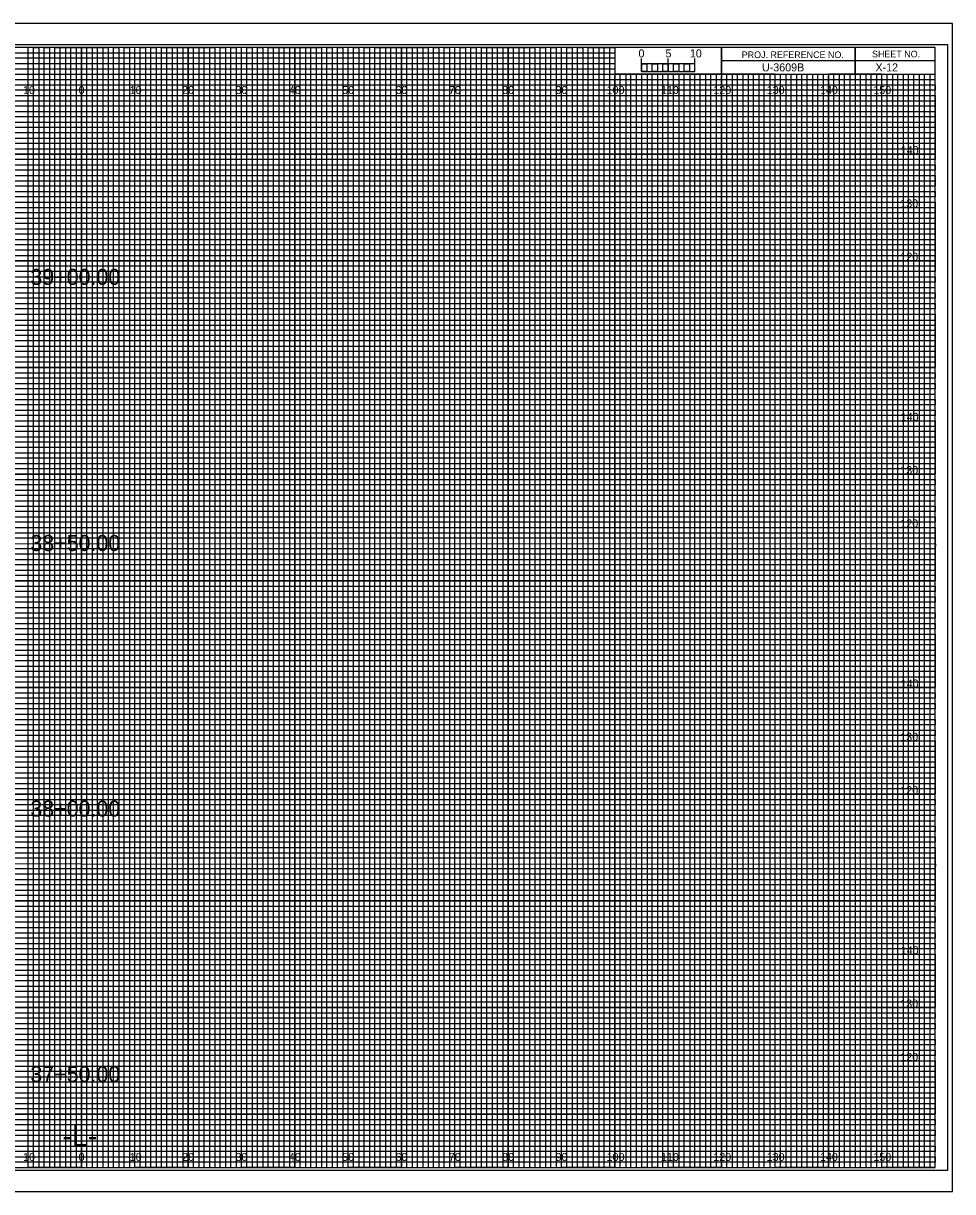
# Model space of a CAD drawing. Extents: x -13 to 329, y -17 to 10994.
# Drawn here: x 149.1 to 323.3, y 2195.5 to 2414.5 of the extents above; entities that cross this region are included whole.
import ezdxf

# ---------------------------------------------------------------- set-up
doc = ezdxf.new("R2010")
doc.units = 0
for name, color, linetype in [('Prop XS Alignment Label', 7, 'Continuous'), ('Prop XS Bar Scale Labels', 7, 'Continuous'), ('Prop XS Elevation Labels', 7, 'Continuous'), ('Prop XS Offset Labels', 7, 'Continuous'), ('Prop XS Project Number', 7, 'Continuous'), ('Prop XS Sheet Number', 7, 'Continuous'), ('Prop XS Station Labels', 7, 'Continuous'), ('Sheet Cross Section CELL', 7, 'Continuous'), ('Sheet Cross Section Grid Major CELL', 7, 'Continuous'), ('Sheet Cross Section Grid Middle CELL', 7, 'Continuous'), ('Sheet Cross Section Grid Minor 1 CELL', 7, 'Continuous'), ('Sheet Cross Section Grid Minor 2 CELL', 7, 'Continuous'), ('Sheet Cross Section Scale CELL', 7, 'Continuous'), ('Sheet Cutting Line CELL', 7, 'Continuous'), ('Sheet DOT Grid CELL', 7, 'Continuous'), ('Sheet Plot Border Inside CELL', 7, 'Continuous'), ('Sheet Plot Border Outside CELL', 7, 'Continuous')]:
    doc.layers.add(name, color=color, linetype=linetype)

msp = doc.modelspace()

# ---------------------------------------------------------------- linework, layer by layer
at = {"layer": 'Sheet Cross Section CELL'}
for p, q in [((305, 2410), (305, 2405)), ((305, 2405), (305, 2410)), ((280, 2407.5), (280, 2405)), ((320, 2407.49), (280, 2407.49)), ((280, 2405), (320, 2405))]:
    msp.add_line(p, q, dxfattribs=at)
for points in [[(320, 2410), (0, 2410), (0, 2200), (320, 2200)], [(280, 2410), (260, 2410), (260, 2405.03), (280, 2405.03)], [(320, 2410), (280, 2410), (280, 2405), (320, 2405)]]:
    msp.add_lwpolyline(points, close=True, dxfattribs=at)
at = {"layer": 'Sheet Cross Section Grid Major CELL'}
for p, q in [((150, 2410), (140, 2410)), ((150, 2200), (150, 2410)), ((170, 2410), (160, 2410)), ((160, 2410), (160, 2200)), ((170, 2200), (170, 2410)), ((190, 2410), (180, 2410)), ((180, 2410), (180, 2200)), ((190, 2200), (190, 2410)), ((210, 2410), (200, 2410)), ((200, 2410), (200, 2200)), ((210, 2200), (210, 2410)), ((230, 2410), (220, 2410)), ((220, 2410), (220, 2200)), ((230, 2200), (230, 2410)), ((250, 2410), (240, 2410)), ((240, 2410), (240, 2200)), ((250, 2200), (250, 2410)), ((260, 2410), (260, 2200)), ((270, 2200), (270, 2405)), ((290, 2405), (280, 2405)), ((280, 2405), (280, 2200)), ((290, 2200), (290, 2405)), ((310, 2405), (300, 2405)), ((300, 2405), (300, 2200)), ((310, 2200), (310, 2405)), ((160, 2200), (150, 2200)), ((180, 2200), (170, 2200)), ((200, 2200), (190, 2200)), ((220, 2200), (210, 2200)), ((240, 2200), (230, 2200)), ((260, 2200), (250, 2200)), ((280, 2200), (270, 2200)), ((300, 2200), (290, 2200)), ((320, 2200), (310, 2200)), ((320, 2200), (320, 2200))]:
    msp.add_line(p, q, dxfattribs=at)
for points in [[(0, 2400), (320, 2400), (320, 2390), (0, 2390)], [(0, 2380), (320, 2380), (320, 2370), (0, 2370)], [(0, 2360), (320, 2360), (320, 2350), (0, 2350)], [(0, 2340), (320, 2340), (320, 2330), (0, 2330)], [(0, 2320), (320, 2320), (320, 2310), (0, 2310)], [(0, 2300), (320, 2300), (320, 2290), (0, 2290)], [(0, 2280), (320, 2280), (320, 2270), (0, 2270)], [(0, 2260), (320, 2260), (320, 2250), (0, 2250)], [(0, 2240), (320, 2240), (320, 2230), (0, 2230)], [(0, 2220), (320, 2220), (320, 2210), (0, 2210)]]:
    msp.add_lwpolyline(points, dxfattribs=at)
at = {"layer": 'Sheet Cross Section Grid Middle CELL'}
for points in [[(145, 2200), (155, 2200), (155, 2410), (165, 2410), (165, 2200), (175, 2200), (175, 2410), (185, 2410), (185, 2200), (195, 2200), (195, 2410), (205, 2410), (205, 2200), (215, 2200), (215, 2410), (225, 2410), (225, 2200), (235, 2200), (235, 2410), (245, 2410), (245, 2200), (255, 2200), (255, 2410), (259.93, 2410), (260, 2410), (260, 2405), (264.99, 2405), (264.99, 2200), (275, 2200), (275, 2405), (285, 2405), (285, 2200), (295, 2200), (295, 2405), (305, 2405), (305, 2200), (315, 2200), (315, 2405)], [(0, 2405), (275, 2405)], [(0, 2385), (320, 2385), (320, 2395), (0, 2395)], [(0, 2365), (320, 2365), (320, 2375), (0, 2375)], [(0, 2345), (320, 2345), (320, 2355), (0, 2355)], [(0, 2325), (320, 2325), (320, 2335), (0, 2335)], [(0, 2305), (320, 2305), (320, 2315), (0, 2315)], [(0, 2285), (320, 2285), (320, 2295), (0, 2295)], [(0, 2265), (320, 2265), (320, 2275), (0, 2275)], [(0, 2245), (320, 2245), (320, 2255), (0, 2255)], [(0, 2225), (320, 2225), (320, 2235), (0, 2235)], [(0, 2205), (320, 2205), (320, 2215), (0, 2215)]]:
    msp.add_lwpolyline(points, dxfattribs=at)
at = {"layer": 'Sheet Cross Section Grid Minor 1 CELL'}
for p, q in [((0, 2409), (260, 2409)), ((260, 2409), (260, 2407.98)), ((260, 2407.98), (0, 2407.98)), ((0, 2407), (260, 2407)), ((260, 2407), (260, 2405.89)), ((260, 2405.89), (0, 2405.89)), ((0, 2404), (320, 2404))]:
    msp.add_line(p, q, dxfattribs=at)
for points in [[(0, 2403), (270, 2403), (320, 2403), (320, 2402), (0, 2402)], [(0, 2401), (320, 2401), (320, 2399), (0, 2399)], [(0, 2398), (320, 2398), (320, 2397), (0, 2396.98)], [(0, 2396), (320, 2396), (320, 2394), (0, 2394)], [(0, 2393), (320, 2393), (320, 2392), (0, 2392)], [(0, 2391), (320, 2391), (320, 2389), (0, 2389)], [(0, 2388), (320, 2388), (320, 2387), (0, 2387)], [(0, 2386), (320, 2386), (320, 2384), (0, 2384)], [(0, 2383), (320, 2383), (320, 2382), (0, 2382)], [(0, 2381), (320, 2381), (320, 2379), (0, 2379)], [(0, 2378), (320, 2378), (320, 2377), (0, 2377)], [(0, 2376), (320, 2376), (320, 2373.95), (320, 2373), (320, 2372), (0, 2372)], [(0, 2374), (320, 2374), (320, 2373), (0, 2373)], [(0, 2371), (320, 2371), (320, 2369), (0, 2369.03)], [(0, 2369.03), (320, 2369), (320, 2368), (0, 2368)], [(0, 2367), (320, 2367), (320, 2366), (0, 2366)], [(0, 2364), (320, 2364), (320, 2363), (0, 2363)], [(0, 2362), (320, 2362), (320, 2361), (0, 2361)], [(-0.07, 2358.89), (320, 2358.89), (320, 2357.88), (-0.07, 2357.88)], [(0, 2357), (320, 2357), (320, 2356), (0, 2356)], [(0, 2354), (320, 2354), (320, 2353), (0, 2353)], [(0, 2352), (320, 2352), (320, 2351), (0, 2351)], [(0, 2349), (320, 2349), (320, 2348), (0, 2348)], [(0, 2347), (320, 2347), (320, 2346), (0, 2346)], [(0, 2344), (320, 2344), (320, 2343), (0, 2343)], [(0, 2342), (320, 2342), (320, 2341), (0, 2341)], [(0, 2339), (320, 2339), (319.99, 2337.98), (0, 2338)], [(0, 2337), (320, 2337), (320, 2336), (0, 2336)], [(0, 2334), (320, 2334), (320, 2333), (0, 2333)], [(0, 2332), (320, 2332), (320, 2331), (0, 2331)], [(0, 2329), (320, 2329), (320, 2328), (0, 2328)], [(0, 2327), (320, 2327), (320, 2326), (0, 2326)], [(0, 2324), (320, 2324), (320, 2323), (0, 2323)], [(0, 2322), (320, 2322), (320, 2321), (0, 2321)], [(0, 2319), (320, 2319), (320, 2318), (0, 2318)], [(0, 2316.99), (320.07, 2316.91), (320, 2316), (0, 2316)], [(0, 2314), (320, 2314), (320, 2313), (0, 2313)], [(0, 2312), (320, 2312), (320, 2311), (0, 2311)], [(0, 2309), (320, 2309), (320, 2308), (0, 2308)], [(0, 2307), (320, 2307), (320, 2306), (0, 2306)], [(0, 2304), (320, 2304), (320, 2303), (0, 2303)], [(0, 2302), (320, 2302), (320, 2301), (0, 2301)], [(0, 2299), (320, 2299), (320, 2298), (0, 2298)], [(0, 2297), (320, 2297), (320, 2296), (0, 2296)], [(0, 2294), (320, 2294), (320, 2293), (0, 2293)], [(0, 2292), (320, 2292), (320, 2291), (0, 2291)], [(0, 2289), (320, 2289), (320, 2288), (0, 2288)], [(0, 2287), (320, 2287), (320, 2286), (0, 2286)], [(0, 2284), (320, 2284), (320, 2283), (0, 2283)], [(0, 2282), (320, 2282), (320, 2281), (0, 2281)], [(0, 2279), (320, 2279), (319.99, 2277.98), (0, 2278)], [(0, 2277), (320, 2277), (320, 2276), (0, 2276)], [(0, 2274), (320, 2274), (320, 2273), (0, 2273)], [(0, 2272), (320, 2272), (320, 2271), (0, 2271)], [(0, 2269), (320, 2269), (320, 2268), (0, 2268)], [(0, 2267), (320, 2267), (320, 2266), (0, 2266)], [(0, 2264), (320, 2264), (320, 2263), (0, 2263)], [(0, 2262), (320, 2262), (320, 2261), (0, 2261)], [(0, 2259), (320, 2259), (320, 2258), (0, 2258)], [(0, 2256.99), (320.07, 2256.91), (320, 2256), (0, 2256)], [(0, 2254), (320, 2254), (320, 2253), (0, 2253)], [(0, 2252), (320, 2252), (320, 2251), (0, 2251)], [(0, 2249), (320, 2249), (320, 2248), (0, 2248)], [(0, 2247), (320, 2247), (320, 2246), (0, 2246)], [(0, 2244), (320, 2244), (320, 2243), (0, 2243)], [(0, 2242), (320, 2242), (320, 2241), (0, 2241)], [(0, 2239), (320, 2239), (320, 2238), (0, 2238)], [(0, 2237), (320, 2237), (320, 2236), (0, 2236)], [(0, 2234), (320, 2234), (320, 2233), (0, 2233)], [(0, 2232), (320, 2232), (320, 2231), (0, 2231)], [(0, 2229), (320, 2229), (320, 2228), (0, 2228)], [(0, 2227), (320, 2227), (320, 2226), (0, 2226)], [(0, 2224), (320, 2224), (320, 2223), (0, 2223)], [(0, 2222), (320, 2222), (320, 2221), (0, 2221)], [(0, 2219), (320, 2219), (320, 2218), (0, 2218)], [(0, 2217), (320, 2217), (320, 2216), (0, 2216)], [(0, 2214), (320, 2214), (320, 2213), (0, 2213)], [(0, 2212), (320, 2212), (320, 2211), (0, 2211)], [(0, 2209), (320, 2209), (320, 2208), (0, 2208)], [(0, 2207), (320, 2207), (320, 2206), (0, 2206)], [(0, 2204), (320, 2204), (320, 2203), (0, 2203)], [(0, 2202), (320, 2202), (320, 2201), (0, 2201)]]:
    msp.add_lwpolyline(points, dxfattribs=at)
at = {"layer": 'Sheet Cross Section Grid Minor 2 CELL'}
for p, q in [((267, 2405), (266.01, 2405)), ((266.01, 2405), (266.01, 2200)), ((267, 2200), (267, 2405)), ((269, 2405), (268, 2405)), ((268, 2405), (268, 2200)), ((269, 2200), (269, 2405)), ((266.01, 2200), (265, 2200)), ((268, 2200), (267, 2200))]:
    msp.add_line(p, q, dxfattribs=at)
for points in [[(150, 2200), (151, 2200), (151, 2410), (152, 2410), (152, 2200)], [(152, 2200), (153, 2200), (153, 2410), (154, 2410), (154, 2200)], [(155, 2200), (156, 2200), (156, 2410), (157, 2410), (157, 2200)], [(157, 2200), (158, 2200), (158, 2410), (159, 2410), (159, 2200)], [(160, 2200), (161, 2200), (161, 2410), (162, 2410), (162, 2200)], [(162, 2200), (163, 2200), (163, 2410), (164, 2410), (164, 2200)], [(165, 2200), (166, 2200), (166, 2410), (167, 2410), (167, 2200)], [(167, 2200), (168, 2200), (168, 2410), (169, 2410), (169, 2200)], [(170, 2200), (171, 2200), (171, 2410), (172, 2410), (172, 2200)], [(172, 2200), (173, 2200), (173, 2410), (174, 2410), (174, 2200)], [(175, 2200), (176, 2200), (176, 2410), (177, 2410), (177, 2200)], [(177, 2200), (178, 2200), (178, 2410), (179, 2410), (179, 2200)], [(180, 2200), (181, 2200), (181, 2410), (182, 2410), (182, 2200)], [(182, 2200), (183, 2200), (183, 2410), (184, 2410), (184, 2200)], [(185, 2200), (186, 2200), (186, 2410), (187, 2410), (187, 2200)], [(187, 2200), (188, 2200), (188, 2410), (189, 2410), (189, 2200)], [(190, 2200), (191, 2200), (191, 2410), (192, 2410), (192, 2200)], [(192, 2200), (193, 2200), (193, 2410), (194, 2410), (194, 2200)], [(195, 2200), (196, 2200), (196, 2410), (197, 2410), (197, 2200)], [(197, 2200), (198, 2200), (198, 2410), (199, 2410), (199, 2200)], [(200, 2200), (201, 2200), (201, 2410), (202, 2410), (202, 2200)], [(202, 2200), (203, 2200), (203, 2410), (204, 2410), (204, 2200)], [(205, 2200), (206, 2200), (206, 2410), (207, 2410), (207, 2200)], [(207, 2200), (208, 2200), (208, 2410), (209, 2410), (209, 2200)], [(210, 2200), (211, 2200), (211, 2410), (212, 2410), (212, 2200)], [(212, 2200), (213, 2200), (213, 2410), (214, 2410), (214, 2200)], [(215, 2200), (216, 2200), (216, 2410), (217, 2410), (217, 2200)], [(217, 2200), (218, 2200), (218, 2410), (219, 2410), (219, 2200)], [(220, 2200), (221, 2200), (221, 2410), (222, 2410), (222, 2200)], [(222, 2200), (223, 2200), (223, 2410), (224, 2410), (224, 2200)], [(225, 2200), (226, 2200), (226, 2410), (227, 2410), (227, 2200)], [(227, 2200), (228, 2200), (228, 2410), (229, 2410), (229, 2200)], [(230, 2200), (231, 2200), (231, 2410), (232, 2410), (232, 2200)], [(232, 2200), (233, 2200), (233, 2410), (234, 2410), (234, 2200)], [(235, 2200), (236, 2200), (236, 2410), (237, 2410), (237, 2200)], [(237, 2200), (238, 2200), (238, 2410), (239, 2410), (239, 2200)], [(240, 2200), (241, 2200), (241, 2410), (242, 2410), (242, 2200)], [(242, 2200), (243, 2200), (243, 2410), (244, 2410), (244, 2200)], [(245, 2200), (246, 2200), (246, 2410), (247, 2410), (247, 2200)], [(247, 2200), (248, 2200), (248, 2410), (249, 2410), (249, 2200)], [(250, 2200), (251, 2200), (251, 2410), (252, 2410), (252, 2200)], [(252, 2200), (253, 2200), (253, 2410), (254, 2410), (254, 2200)], [(255, 2200), (256, 2200), (256, 2410), (257, 2410), (257, 2200)], [(257, 2200), (258, 2200), (258, 2410), (259, 2410), (259, 2200)], [(260, 2200), (261, 2200), (261, 2405), (262.02, 2405), (262.02, 2200)], [(262, 2200), (263, 2200), (263, 2405), (263.99, 2405), (263.99, 2200)], [(270, 2200), (270.98, 2200), (270.98, 2405), (272, 2405), (272, 2200)], [(272, 2200), (273, 2200), (273, 2405), (274.05, 2405), (274.05, 2200)], [(275, 2200), (276, 2200), (276, 2405), (277, 2405), (277, 2200)], [(277, 2200), (278, 2200), (278, 2405), (279, 2405), (279, 2200)], [(280, 2200), (281, 2200), (281, 2405), (282, 2405), (282, 2200)], [(282, 2200), (283, 2200), (283, 2405), (284, 2405), (284, 2200)], [(285, 2200), (286, 2200), (286, 2405), (287, 2405), (287, 2200)], [(287, 2200), (288, 2200), (288, 2405), (289, 2405), (289, 2200)], [(290, 2200), (291, 2200), (291, 2405), (292, 2405), (292, 2200)], [(292, 2200), (293, 2200), (293, 2405), (294, 2405), (294, 2200)], [(295, 2200), (296, 2200), (296, 2405), (297, 2405), (297, 2200)], [(297, 2200), (298, 2200), (298, 2405), (299, 2405), (299, 2200)], [(300, 2200), (301, 2200), (301, 2405), (302, 2405), (302, 2200)], [(302, 2200), (303, 2200), (303, 2405), (304, 2405), (304, 2200)], [(305, 2200), (306, 2200), (306, 2405), (307, 2405), (307, 2200)], [(307, 2200), (308, 2200), (308, 2405), (309, 2405), (309, 2200)], [(310, 2200), (311, 2200), (311, 2405), (312, 2405), (312, 2200)], [(312, 2200), (313, 2200), (313, 2405), (314, 2405), (314, 2200)], [(315, 2200), (316, 2200), (316, 2405), (317, 2405), (317, 2200)], [(317, 2200), (318, 2200), (318, 2405), (319, 2405), (319, 2200)]]:
    msp.add_lwpolyline(points, dxfattribs=at)
at = {"layer": 'Sheet Cross Section Scale CELL'}
for p, q in [((265, 2405.49), (265, 2407.9)), ((265, 2406.9), (265, 2407.9)), ((270, 2405.49), (270, 2407.9)), ((275, 2405.49), (275, 2407.9)), ((275, 2406.9), (275, 2407.9))]:
    msp.add_line(p, q, dxfattribs=at)
for points in [[(275, 2406.9), (265, 2406.9), (265, 2405.49), (275, 2405.49)], [(265, 2406.9), (266, 2406.9), (266, 2405.49), (265, 2405.49)], [(267, 2406.9), (268, 2406.9), (268, 2405.49), (267, 2405.49)], [(269, 2406.9), (270, 2406.9), (270, 2405.49), (269, 2405.49)], [(271, 2406.9), (272, 2406.9), (272, 2405.49), (271, 2405.49)], [(273, 2406.9), (274, 2406.9), (274, 2405.49), (273, 2405.49)]]:
    msp.add_lwpolyline(points, close=True, dxfattribs=at)
at = {"layer": 'Sheet Cutting Line CELL'}
for p, q in [((323.3, 2414.5), (-13.4, 2414.5)), ((-13.4, 2195.5), (323.3, 2195.5))]:
    msp.add_line(p, q, dxfattribs=at)
at = {"layer": 'Sheet DOT Grid CELL'}
for p, q in [((150, 2200), (150, 2410)), ((160, 2200), (160, 2410)), ((170, 2200), (170, 2410)), ((180, 2200), (180, 2410)), ((190, 2200), (190, 2410)), ((200, 2200), (200, 2410)), ((210, 2200), (210, 2410)), ((220, 2200), (220, 2410)), ((230, 2200), (230, 2410)), ((240, 2200), (240, 2410)), ((250, 2200), (250, 2410)), ((260, 2200), (260, 2404.69)), ((270, 2200), (270, 2404.69)), ((280, 2200), (280, 2404.69)), ((290, 2200), (290, 2404.69)), ((300, 2200), (300, 2404.69)), ((310, 2200), (310, 2404.69)), ((0, 2400), (320, 2400)), ((0, 2390), (320, 2390)), ((0, 2380), (320, 2380)), ((0, 2370), (320, 2370)), ((0, 2360), (320, 2360)), ((0, 2350), (320, 2350)), ((0, 2340), (320, 2340)), ((0, 2330), (320, 2330)), ((0, 2320), (320, 2320)), ((0, 2310), (320, 2310)), ((0, 2300), (320, 2300)), ((0, 2290), (320, 2290)), ((0, 2280), (320, 2280)), ((0, 2270), (320, 2270)), ((0, 2260), (320, 2260)), ((0, 2250), (320, 2250)), ((0, 2240), (320, 2240)), ((0, 2230), (320, 2230)), ((0, 2220), (320, 2220)), ((0, 2210), (320, 2210))]:
    msp.add_line(p, q, dxfattribs=at)
at = {"layer": 'Sheet Plot Border Inside CELL'}
msp.add_lwpolyline([(-10.8, 2199.5), (322.4, 2199.5), (322.4, 2410.5), (-10.8, 2410.5)], close=True, dxfattribs=at)
at = {"layer": 'Sheet Plot Border Outside CELL'}
msp.add_lwpolyline([(-13.4, 2195.5), (323.3, 2195.5), (323.3, 2414.5), (-13.4, 2414.5)], close=True, dxfattribs=at)

# ---------------------------------------------------------------- texts
at = {"layer": 'Prop XS Alignment Label'}
msp.add_text('-L-', height=4, dxfattribs=at).set_placement((156.42, 2204))
at = {"layer": 'Prop XS Bar Scale Labels'}
for s, p in [('5', (269.47, 2408.12)), ('10', (274.04, 2408.12))]:
    msp.add_text(s, height=1.5, dxfattribs=at).set_placement(p)
at = {"layer": 'Prop XS Elevation Labels'}
for s, p in [('140', (313.57, 2390)), ('130', (313.49, 2380)), ('120', (313.5, 2370)), ('140', (313.57, 2340)), ('130', (313.49, 2330)), ('120', (313.5, 2320)), ('140', (313.57, 2290)), ('130', (313.49, 2280)), ('120', (313.5, 2270)), ('140', (313.57, 2240)), ('130', (313.49, 2230)), ('120', (313.5, 2220))]:
    msp.add_text(s, height=1.5, dxfattribs=at).set_placement(p)
at = {"layer": 'Prop XS Offset Labels'}
for s, p in [('10', (149.04, 2401.25)), ('0', (159.45, 2401.25)), ('0', (159.45, 2401.25)), ('10', (169.04, 2401.25)), ('20', (178.86, 2401.25)), ('30', (188.86, 2401.25)), ('40', (198.86, 2401.25)), ('50', (208.86, 2401.25)), ('60', (218.86, 2401.25)), ('70', (228.86, 2401.25)), ('80', (238.86, 2401.25)), ('90', (248.86, 2401.25)), ('100', (258.44, 2401.25)), ('110', (268.62, 2401.25)), ('120', (278.44, 2401.25)), ('130', (288.44, 2401.25)), ('140', (298.44, 2401.25)), ('150', (308.44, 2401.25)), ('10', (149.04, 2201.25)), ('0', (159.45, 2201.25)), ('0', (159.45, 2201.25)), ('10', (169.04, 2201.25)), ('20', (178.86, 2201.25)), ('30', (188.86, 2201.25)), ('40', (198.86, 2201.25)), ('50', (208.86, 2201.25)), ('60', (218.86, 2201.25)), ('70', (228.86, 2201.25)), ('80', (238.86, 2201.25)), ('90', (248.86, 2201.25)), ('100', (258.44, 2201.25)), ('110', (268.62, 2201.25)), ('120', (278.44, 2201.25)), ('130', (288.44, 2201.25)), ('140', (298.44, 2201.25)), ('150', (308.44, 2201.25))]:
    msp.add_text(s, height=1.5, dxfattribs=at).set_placement(p)
at = {"layer": 'Prop XS Project Number'}
msp.add_text('U-3609B', height=1.5, dxfattribs=at).set_placement((287.56, 2405.5))
at = {"layer": 'Prop XS Sheet Number'}
msp.add_text('X-12', height=1.5, dxfattribs=at).set_placement((308.83, 2405.5))
at = {"layer": 'Prop XS Station Labels'}
for s, p in [('39+00.00', (150.41, 2365.47)), ('38+50.00', (150.41, 2315.59)), ('38+00.00', (150.41, 2265.8)), ('37+50.00', (150.41, 2216.03))]:
    msp.add_text(s, height=3, dxfattribs=at).set_placement(p)
at = {"layer": 'Sheet Cross Section CELL'}
for s, p in [('PROJ. REFERENCE NO.', (283.77, 2407.99)), ('SHEET NO.', (308.19, 2408.12))]:
    msp.add_text(s, height=1.25, dxfattribs=at).set_placement(p)
at = {"layer": 'Sheet Cross Section Scale CELL'}
msp.add_text('0', height=1.5, dxfattribs=at).set_placement((264.41, 2408.12))

doc.saveas('drawing.dxf')
